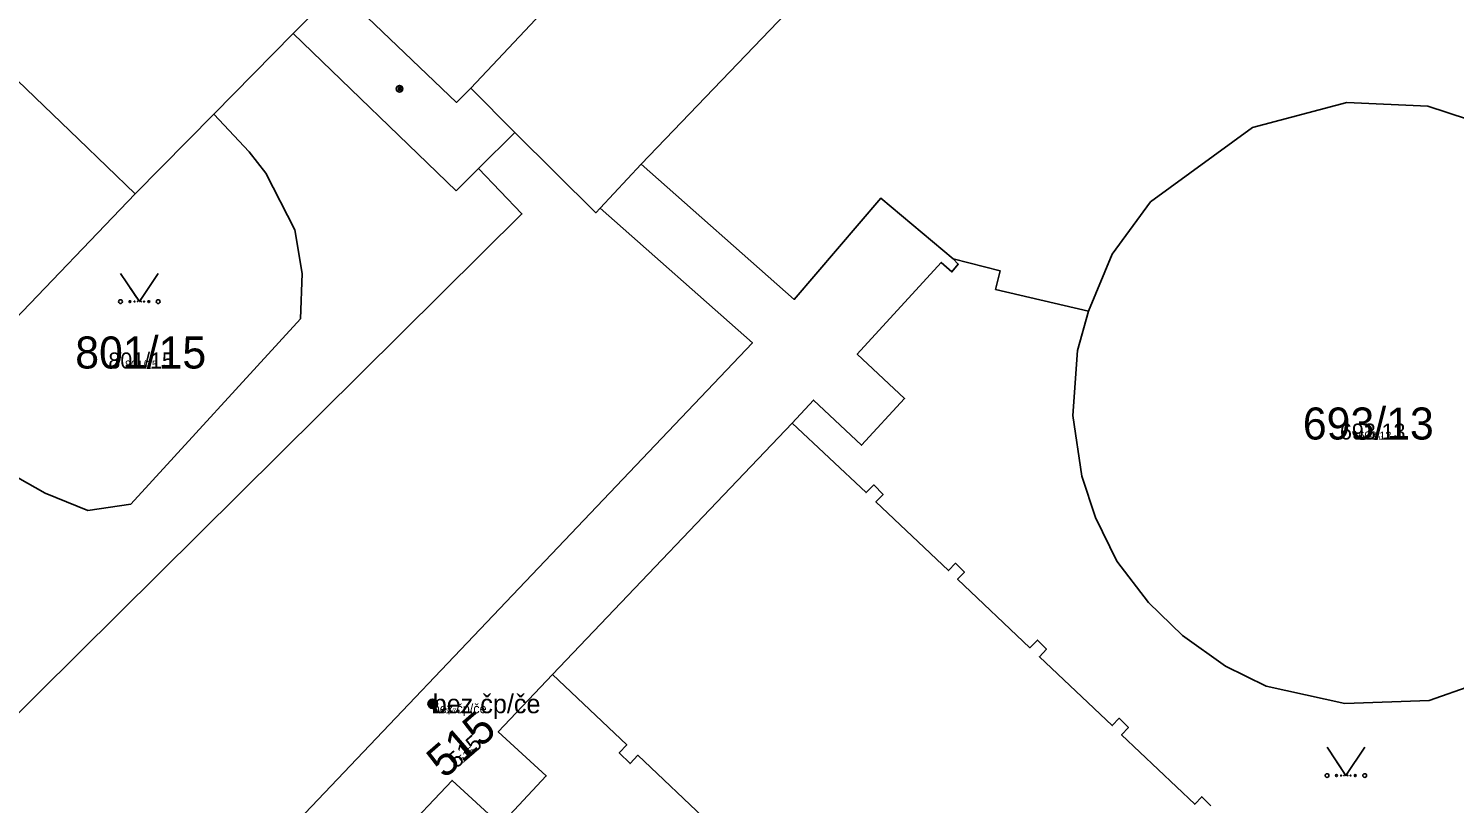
# Model space of a CAD drawing. Extents: x -744652 to -739090, y -980828 to -975855.
# Drawn here: x -743707.2 to -743631.5, y -978224.5 to -978183.4 of the extents above; entities that cross this region are included whole.
import ezdxf

# ---------------------------------------------------------------- set-up
doc = ezdxf.new("R2010")
doc.units = 0
for name, color, linetype in [('KAT_02_hranice parcel', 7, 'Continuous'), ('KAT_03_1000_st čísla parcelní', 7, 'Continuous'), ('KAT_03_1000_čísla parcelní', 7, 'Continuous'), ('KAT_03_1000_čísla popisná', 7, 'Continuous'), ('KAT_03_100_st čísla parcelní', 7, 'Continuous'), ('KAT_03_100_čísla parcelní', 7, 'Continuous'), ('KAT_03_100_čísla popisná', 7, 'Continuous'), ('KAT_03_250_st čísla parcelní', 7, 'Continuous'), ('KAT_03_250_čísla parcelní', 7, 'Continuous'), ('KAT_03_250_čísla popisná', 7, 'Continuous'), ('KAT_03_500_st čísla parcelní', 7, 'Continuous'), ('KAT_03_500_čísla parcelní', 7, 'Continuous'), ('KAT_03_500_čísla popisná', 7, 'Continuous'), ('KAT_04_vnitřní kresba', 7, 'Continuous'), ('KAT_05_1000_značky kultur', 7, 'Continuous'), ('KAT_05_100_značky kultur', 7, 'Continuous'), ('KAT_05_250_značky kultur', 7, 'Continuous'), ('KAT_05_500_značky kultur', 7, 'Continuous'), ('KAT_07_1000_značky budov', 7, 'Continuous'), ('KAT_07_100_značky budov', 7, 'Continuous'), ('KAT_07_500_značky budov', 7, 'Continuous'), ('KAT_14_plocha_budovy', 7, 'Continuous')]:
    doc.layers.add(name, color=color, linetype=linetype)

msp = doc.modelspace()

# ---------------------------------------------------------------- linework, layer by layer
at = {"layer": 'KAT_02_hranice parcel'}
for p, q in [((-743693.17, -978183.62), (-743690.8, -978181.24)), ((-743693.17, -978183.62), (-743697.39, -978187.9)), ((-743684.52, -978191.96), (-743693.17, -978183.62)), ((-743701.56, -978192.12), (-743697.39, -978187.9)), ((-743681.39, -978188.87), (-743683.33, -978190.78)), ((-743683.33, -978190.78), (-743684.52, -978191.96)), ((-743676.86, -978192.88), (-743674.68, -978190.55)), ((-743708.35, -978199.2), (-743701.56, -978192.12)), ((-743666.66, -978204.3), (-743679.39, -978217.64))]:
    msp.add_line(p, q, dxfattribs=at)
for points in [[(-743756.55, -978137.79), (-743757.28, -978138.56), (-743704.58, -978189.22), (-743701.56, -978192.12)], [(-743650.01, -978166.8), (-743651.6, -978166.5), (-743674.68, -978190.55)], [(-743690.8, -978181.24), (-743684.5, -978187.27), (-743683.73, -978186.52), (-743680.3, -978182.88), (-743678.03, -978180.56)], [(-743697.39, -978187.9), (-743695.5, -978189.9), (-743694.63, -978191.03), (-743693.09, -978194.04), (-743692.69, -978196.35), (-743692.79, -978198.76), (-743701.8, -978208.61), (-743704.07, -978208.94), (-743706.35, -978208.01), (-743707.81, -978207.18), (-743712.5, -978203.52)], [(-743650.93, -978198.35), (-743649.67, -978195.33), (-743647.64, -978192.56), (-743642.22, -978188.6), (-743637.2, -978187.28), (-743632.91, -978187.48), (-743628.7, -978188.85), (-743625.41, -978191.02), (-743623.18, -978193.3), (-743621.47, -978196.01), (-743620.41, -978198.76)], [(-743676.86, -978192.88), (-743677.1, -978193.13), (-743681.39, -978188.87)], [(-743683.33, -978190.78), (-743681.02, -978193.19), (-743764.58, -978275.98)], [(-743674.68, -978190.55), (-743666.56, -978197.73), (-743661.96, -978192.36), (-743658.11, -978195.58)], [(-743700.96, -978239.74), (-743700.65, -978239.4), (-743703.56, -978236.6), (-743668.78, -978200.04), (-743676.86, -978192.88)], [(-743666.66, -978204.3), (-743665.54, -978203.08), (-743662.99, -978205.47), (-743660.7, -978203), (-743663.21, -978200.63), (-743658.75, -978195.77), (-743658.18, -978196.27), (-743657.85, -978195.86), (-743658.11, -978195.58)], [(-743658.11, -978195.58), (-743655.62, -978196.22), (-743655.86, -978197.2), (-743650.93, -978198.35)], [(-743650.93, -978198.35), (-743651.51, -978200.45), (-743651.76, -978203.9), (-743651.29, -978207.12), (-743650.56, -978209.31), (-743649.42, -978211.62), (-743647.75, -978213.83), (-743645.93, -978215.58), (-743643.65, -978217.2), (-743641.49, -978218.26), (-743637.31, -978219.19), (-743632.83, -978219.02), (-743628.2, -978217.39), (-743626.95, -978216.6), (-743624.86, -978214.98), (-743622.86, -978212.83), (-743621.26, -978210.15), (-743620.28, -978207.47), (-743619.77, -978204.65), (-743619.78, -978201.89), (-743620.41, -978198.76)], [(-743644.43, -978224.61), (-743644.91, -978224.13), (-743645.29, -978224.53), (-743649.17, -978220.84), (-743648.81, -978220.46), (-743649.3, -978219.97), (-743649.67, -978220.36), (-743653.54, -978216.7), (-743653.16, -978216.3), (-743653.64, -978215.82), (-743654.04, -978216.22), (-743657.88, -978212.59), (-743657.52, -978212.21), (-743658, -978211.74), (-743658.37, -978212.13), (-743662.22, -978208.48), (-743661.84, -978208.08), (-743662.33, -978207.58), (-743662.74, -978207.99), (-743666.66, -978204.3)], [(-743687.58, -978226.28), (-743684.73, -978223.27), (-743682.16, -978225.62), (-743679.73, -978223.03), (-743682.28, -978220.69), (-743679.39, -978217.64)], [(-743679.39, -978217.64), (-743675.45, -978221.38), (-743675.85, -978221.8), (-743675.28, -978222.37), (-743674.87, -978221.93), (-743671.06, -978225.54)]]:
    msp.add_lwpolyline(points, dxfattribs=at)
at = {"layer": 'KAT_03_1000_čísla popisná'}
msp.add_circle((-743685.76, -978219.2), 0.25, dxfattribs=at)
msp.add_circle((-743685.76, -978219.2), 0.25, dxfattribs=at)
at = {"layer": 'KAT_03_100_čísla popisná'}
msp.add_circle((-743685.76, -978219.2), 0.025, dxfattribs=at)
msp.add_circle((-743685.76, -978219.2), 0.025, dxfattribs=at)
at = {"layer": 'KAT_03_250_čísla popisná'}
msp.add_circle((-743685.76, -978219.2), 0.0625, dxfattribs=at)
msp.add_circle((-743685.76, -978219.2), 0.0625, dxfattribs=at)
at = {"layer": 'KAT_03_500_čísla popisná'}
msp.add_circle((-743685.76, -978219.2), 0.125, dxfattribs=at)
msp.add_circle((-743685.76, -978219.2), 0.125, dxfattribs=at)
at = {"layer": 'KAT_04_vnitřní kresba'}
msp.add_line((-743683.73, -978186.52), (-743681.39, -978188.87), dxfattribs=at)
at = {"layer": 'KAT_05_1000_značky kultur'}
for points in [[(-743702.34, -978196.349), (-743701.34, -978197.85), (-743700.34, -978196.349)], [(-743638.26, -978221.509), (-743637.26, -978223.01), (-743636.26, -978221.509)]]:
    msp.add_lwpolyline(points, dxfattribs=at)
for centre in [(-743702.34, -978197.849), (-743700.34, -978197.849), (-743638.26, -978223.009), (-743636.26, -978223.009)]:
    msp.add_circle(centre, 0.1, dxfattribs=at)
at = {"layer": 'KAT_05_100_značky kultur'}
for points in [[(-743701.44, -978197.7), (-743701.34, -978197.85), (-743701.24, -978197.7)], [(-743637.36, -978222.86), (-743637.26, -978223.01), (-743637.16, -978222.86)]]:
    msp.add_lwpolyline(points, dxfattribs=at)
for centre in [(-743701.44, -978197.85), (-743701.24, -978197.85), (-743637.36, -978223.01), (-743637.16, -978223.01)]:
    msp.add_circle(centre, 0.01, dxfattribs=at)
at = {"layer": 'KAT_05_250_značky kultur'}
for points in [[(-743701.59, -978197.475), (-743701.34, -978197.85), (-743701.09, -978197.475)], [(-743637.51, -978222.635), (-743637.26, -978223.01), (-743637.01, -978222.635)]]:
    msp.add_lwpolyline(points, dxfattribs=at)
for centre in [(-743701.59, -978197.85), (-743701.09, -978197.85), (-743637.51, -978223.01), (-743637.01, -978223.01)]:
    msp.add_circle(centre, 0.025, dxfattribs=at)
at = {"layer": 'KAT_05_500_značky kultur'}
for points in [[(-743701.84, -978197.1), (-743701.34, -978197.85), (-743700.84, -978197.1)], [(-743637.76, -978222.26), (-743637.26, -978223.01), (-743636.76, -978222.26)]]:
    msp.add_lwpolyline(points, dxfattribs=at)
for centre in [(-743701.84, -978197.85), (-743700.84, -978197.85), (-743637.76, -978223.01), (-743636.76, -978223.01)]:
    msp.add_circle(centre, 0.05, dxfattribs=at)
at = {"layer": 'KAT_07_1000_značky budov'}
for centre in [(-743687.517, -978186.549), (-743685.767, -978219.199)]:
    msp.add_circle(centre, 0.175, dxfattribs=at)
at = {"layer": 'KAT_07_100_značky budov'}
for centre in [(-743687.511, -978186.55), (-743685.761, -978219.2)]:
    msp.add_circle(centre, 0.0175, dxfattribs=at)
at = {"layer": 'KAT_07_500_značky budov'}
for centre, radius in [((-743687.513, -978186.55), 0.0875), ((-743687.512, -978186.55), 0.0438), ((-743685.763, -978219.2), 0.0875), ((-743685.762, -978219.2), 0.0438)]:
    msp.add_circle(centre, radius, dxfattribs=at)
at = {"layer": 'KAT_14_plocha_budovy'}
for points in [[(-743757.28, -978138.56), (-743704.58, -978189.22), (-743701.56, -978192.12), (-743697.39, -978187.9), (-743693.17, -978183.62), (-743690.8, -978181.24), (-743743.91, -978130.15), (-743745.17, -978128.94), (-743752.99, -978137.11), (-743754.5, -978135.65), (-743756.55, -978137.79)], [(-743680.3, -978182.88), (-743683.73, -978186.52), (-743681.39, -978188.87), (-743677.1, -978193.13), (-743676.86, -978192.88), (-743674.68, -978190.55), (-743651.6, -978166.5), (-743658.29, -978159.95), (-743678.03, -978180.56)]]:
    msp.add_lwpolyline(points, close=True, dxfattribs=at)
for points in [[(-743687.58, -978226.28), (-743684.73, -978223.27), (-743682.16, -978225.62), (-743679.73, -978223.03), (-743682.28, -978220.69), (-743679.39, -978217.64), (-743666.66, -978204.3), (-743665.54, -978203.08), (-743662.99, -978205.47), (-743660.7, -978203), (-743663.21, -978200.63), (-743658.75, -978195.77), (-743658.18, -978196.27), (-743657.85, -978195.86), (-743658.11, -978195.58), (-743661.96, -978192.36), (-743666.56, -978197.73), (-743674.68, -978190.55), (-743676.86, -978192.88), (-743668.78, -978200.04), (-743703.56, -978236.6)], [(-743644.43, -978224.61), (-743644.91, -978224.13), (-743645.29, -978224.53), (-743649.17, -978220.84), (-743648.81, -978220.46), (-743649.3, -978219.97), (-743649.67, -978220.36), (-743653.54, -978216.7), (-743653.16, -978216.3), (-743653.64, -978215.82), (-743654.04, -978216.22), (-743657.88, -978212.59), (-743657.52, -978212.21), (-743658, -978211.74), (-743658.37, -978212.13), (-743662.22, -978208.48), (-743661.84, -978208.08), (-743662.33, -978207.58), (-743662.74, -978207.99), (-743666.66, -978204.3), (-743679.39, -978217.64), (-743675.45, -978221.38), (-743675.85, -978221.8), (-743675.28, -978222.37), (-743674.87, -978221.93), (-743671.06, -978225.54)]]:
    msp.add_lwpolyline(points, dxfattribs=at)

# ---------------------------------------------------------------- texts
at = {"layer": 'KAT_03_1000_st čísla parcelní'}
msp.add_text('515', height=1.7, rotation=41, dxfattribs=at).set_placement((-743685.142, -978223.217))
at = {"layer": 'KAT_03_1000_čísla parcelní'}
for s, p in [('801/15', (-743704.745, -978201.4)), ('693/13', (-743639.545, -978205.17))]:
    msp.add_text(s, height=1.7, dxfattribs=at).set_placement(p)
at = {"layer": 'KAT_03_1000_čísla popisná'}
msp.add_text('bez čp/če', height=1, dxfattribs=at).set_placement((-743685.76, -978219.7))
msp.add_text('515', height=0.017, rotation=41, dxfattribs=at).set_placement((-743683.872, -978222.113))
at = {"layer": 'KAT_03_100_st čísla parcelní'}
msp.add_text('515', height=0.17, rotation=41, dxfattribs=at).set_placement((-743683.987, -978222.213))
at = {"layer": 'KAT_03_100_čísla parcelní'}
for s, p in [('801/15', (-743701.571, -978201.4)), ('693/13', (-743635.991, -978205.17))]:
    msp.add_text(s, height=0.17, dxfattribs=at).set_placement(p)
at = {"layer": 'KAT_03_100_čísla popisná'}
msp.add_text('bez čp/če', height=0.1, dxfattribs=at).set_placement((-743685.76, -978219.7))
msp.add_text('515', height=0.0017, rotation=41, dxfattribs=at).set_placement((-743683.86, -978222.103))
at = {"layer": 'KAT_03_250_st čísla parcelní'}
msp.add_text('515', height=0.425, rotation=41, dxfattribs=at).set_placement((-743684.18, -978222.381))
at = {"layer": 'KAT_03_250_čísla parcelní'}
for s, p in [('801/15', (-743702.1, -978201.4)), ('693/13', (-743636.584, -978205.17))]:
    msp.add_text(s, height=0.425, dxfattribs=at).set_placement(p)
at = {"layer": 'KAT_03_250_čísla popisná'}
msp.add_text('bez čp/če', height=0.25, dxfattribs=at).set_placement((-743685.76, -978219.7))
msp.add_text('515', height=0.00425, rotation=41, dxfattribs=at).set_placement((-743683.862, -978222.105))
at = {"layer": 'KAT_03_500_st čísla parcelní'}
msp.add_text('515', height=0.85, rotation=41, dxfattribs=at).set_placement((-743684.501, -978222.659))
at = {"layer": 'KAT_03_500_čísla parcelní'}
for s, p in [('801/15', (-743702.982, -978201.4)), ('693/13', (-743637.571, -978205.17))]:
    msp.add_text(s, height=0.85, dxfattribs=at).set_placement(p)
at = {"layer": 'KAT_03_500_čísla popisná'}
msp.add_text('bez čp/če', height=0.5, dxfattribs=at).set_placement((-743685.76, -978219.7))
msp.add_text('515', height=0.0085, rotation=41, dxfattribs=at).set_placement((-743683.865, -978222.107))

doc.saveas('drawing.dxf')
